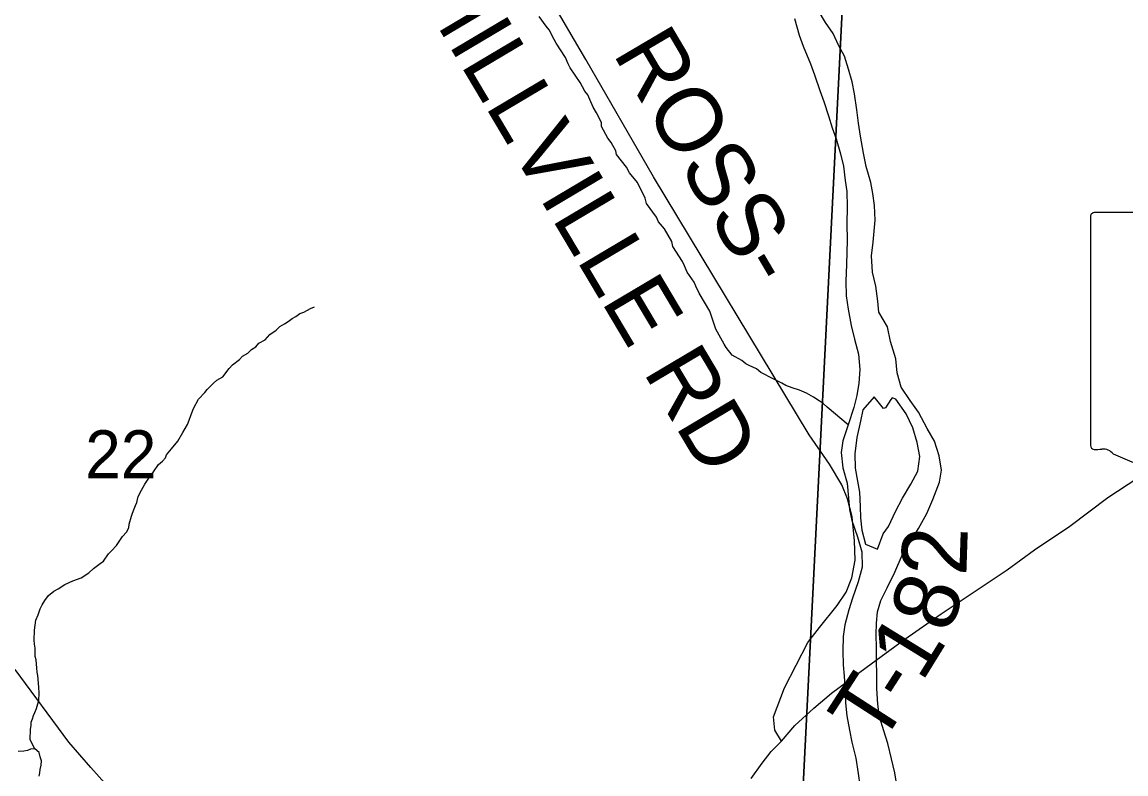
# Model space of a CAD drawing. Extents: x 0 to 34, y -2.3 to 22.
# Drawn here: x 5.851 to 6.815, y 16.564 to 17.221 of the extents above; entities that cross this region are included whole.
import ezdxf

# ---------------------------------------------------------------- set-up
doc = ezdxf.new("R2010")
doc.units = 0
for name, color, linetype in [('GM_X_Major_River', 7, 'Continuous'), ('GM_X_Minor_River', 7, 'Continuous'), ('GM_X_Section', 7, 'Continuous'), ('GM_X_Section_Text', 7, 'Continuous'), ('GM_X_State_Route', 7, 'Continuous'), ('GM_X_State_Shield', 7, 'Continuous'), ('GM_X_Township_Road', 7, 'Continuous'), ('GM_X_Township_Road_Text', 7, 'Continuous')]:
    doc.layers.add(name, color=color, linetype=linetype)

msp = doc.modelspace()

# ---------------------------------------------------------------- linework, layer by layer
at = {"layer": 'GM_X_Major_River'}
for p, q in [((6.55311, 17.22065), (6.54658, 17.23149)), ((6.52585, 17.22411), (6.52997, 17.20954)), ((6.55966, 17.21095), (6.55311, 17.22065)), ((6.52997, 17.20954), (6.53349, 17.19993)), ((6.5643, 17.20093), (6.55966, 17.21095)), ((6.53349, 17.19993), (6.53988, 17.18453)), ((6.56972, 17.19126), (6.5643, 17.20093)), ((6.53988, 17.18453), (6.5434, 17.17492)), ((6.57318, 17.17975), (6.56972, 17.19126)), ((6.5434, 17.17492), (6.54793, 17.1611)), ((6.57627, 17.16864), (6.57318, 17.17975)), ((6.57825, 17.15831), (6.57627, 17.16864)), ((6.54793, 17.1611), (6.55145, 17.15149)), ((6.58049, 17.14417), (6.57825, 17.15831)), ((6.55145, 17.15149), (6.55564, 17.1392)), ((6.55564, 17.1392), (6.55875, 17.12846)), ((6.58167, 17.13273), (6.58049, 17.14417)), ((6.55875, 17.12846), (6.56226, 17.11885)), ((6.58361, 17.12127), (6.58167, 17.13273)), ((6.56226, 17.11885), (6.56606, 17.10581)), ((6.58621, 17.10636), (6.58361, 17.12127)), ((6.58854, 17.09489), (6.58621, 17.10636)), ((6.56606, 17.10581), (6.56878, 17.09509)), ((6.56878, 17.09509), (6.57031, 17.08249)), ((6.59268, 17.0807), (6.58854, 17.09489)), ((6.57031, 17.08249), (6.57155, 17.07295)), ((6.5943, 17.07114), (6.59268, 17.0807)), ((6.57155, 17.07295), (6.57192, 17.05963)), ((6.59589, 17.06083), (6.5943, 17.07114)), ((6.57192, 17.05963), (6.57148, 17.04481)), ((6.59627, 17.04789), (6.59589, 17.06083)), ((6.57148, 17.04481), (6.57182, 17.03035)), ((6.59456, 17.02854), (6.59561, 17.0384)), ((6.59561, 17.0384), (6.59627, 17.04789)), ((6.57182, 17.03035), (6.57119, 17.00908)), ((6.59307, 17.0168), (6.59456, 17.02854)), ((6.59417, 17.00232), (6.59307, 17.0168)), ((6.57119, 17.00908), (6.57076, 16.99464)), ((6.59685, 16.99007), (6.59417, 17.00232)), ((6.57076, 16.99464), (6.57114, 16.9817)), ((6.57114, 16.9817), (6.5727, 16.97025)), ((6.59875, 16.97709), (6.59685, 16.99007)), ((6.5996, 16.96756), (6.59875, 16.97709)), ((6.5727, 16.97025), (6.57532, 16.95572)), ((6.60721, 16.95478), (6.5996, 16.96756)), ((6.57532, 16.95572), (6.57839, 16.94384)), ((6.60986, 16.94178), (6.60721, 16.95478)), ((6.57839, 16.94384), (6.5818, 16.93081)), ((6.61436, 16.92681), (6.60986, 16.94178)), ((6.5818, 16.93081), (6.58293, 16.91747)), ((6.61553, 16.91461), (6.61436, 16.92681)), ((6.58293, 16.91747), (6.58219, 16.90532)), ((6.61895, 16.90196), (6.61553, 16.91461)), ((6.58219, 16.90532), (6.58036, 16.89473)), ((6.58036, 16.89473), (6.57777, 16.88416)), ((6.62697, 16.89032), (6.61895, 16.90196)), ((6.57777, 16.88416), (6.57276, 16.86909)), ((6.59552, 16.89352), (6.58568, 16.88202)), ((6.60358, 16.8834), (6.59552, 16.89352)), ((6.61013, 16.89105), (6.60551, 16.88375)), ((6.61135, 16.89251), (6.61013, 16.89105)), ((6.61446, 16.89145), (6.61135, 16.89251)), ((6.62358, 16.87863), (6.61446, 16.89145)), ((6.63427, 16.88022), (6.62697, 16.89032)), ((6.58568, 16.88202), (6.5835, 16.8722)), ((6.60551, 16.88375), (6.60358, 16.8834)), ((6.6293, 16.86629), (6.62358, 16.87863)), ((6.64183, 16.86593), (6.63427, 16.88022)), ((6.57276, 16.86909), (6.56817, 16.85516)), ((6.5835, 16.8722), (6.58041, 16.85784)), ((6.63311, 16.85363), (6.6293, 16.86629)), ((6.64834, 16.85471), (6.64183, 16.86593)), ((6.56817, 16.85516), (6.56673, 16.84493)), ((6.58041, 16.85784), (6.57848, 16.84383)), ((6.63541, 16.8414), (6.63311, 16.85363)), ((6.65215, 16.84205), (6.64834, 16.85471)), ((6.56673, 16.84493), (6.56824, 16.83158)), ((6.57848, 16.84383), (6.57887, 16.83127)), ((6.63351, 16.82853), (6.63541, 16.8414)), ((6.65443, 16.82943), (6.65215, 16.84205)), ((6.56824, 16.83158), (6.57202, 16.81816)), ((6.57887, 16.83127), (6.58081, 16.8198)), ((6.62748, 16.81729), (6.63351, 16.82853)), ((6.6526, 16.81884), (6.65443, 16.82943)), ((6.57202, 16.81816), (6.57315, 16.80482)), ((6.58081, 16.8198), (6.58281, 16.81024)), ((6.62027, 16.80496), (6.62748, 16.81729)), ((6.64684, 16.8038), (6.6526, 16.81884)), ((6.58281, 16.81024), (6.5832, 16.79768)), ((6.57315, 16.80482), (6.574, 16.79491)), ((6.5832, 16.79768), (6.58367, 16.78778)), ((6.61423, 16.79335), (6.62027, 16.80496)), ((6.64153, 16.7914), (6.64684, 16.8038)), ((6.574, 16.79491), (6.576, 16.78534)), ((6.58367, 16.78778), (6.58487, 16.77709)), ((6.60814, 16.78021), (6.61423, 16.79335)), ((6.63431, 16.77831), (6.64153, 16.7914)), ((6.576, 16.78534), (6.5809, 16.77113)), ((6.6034, 16.77389), (6.60814, 16.78021)), ((6.62593, 16.76486), (6.63431, 16.77831)), ((6.5809, 16.77113), (6.58469, 16.75809)), ((6.58487, 16.77709), (6.58793, 16.76484)), ((6.59844, 16.76035), (6.6034, 16.77389)), ((6.58793, 16.76484), (6.59844, 16.76035)), ((6.61995, 16.75515), (6.62593, 16.76486)), ((6.58469, 16.75809), (6.58506, 16.74477)), ((6.61343, 16.74013), (6.61995, 16.75515)), ((6.58506, 16.74477), (6.58164, 16.73194)), ((6.60695, 16.72663), (6.61343, 16.74013)), ((6.58164, 16.73194), (6.57666, 16.71763)), ((6.60129, 16.71539), (6.60695, 16.72663)), ((6.57666, 16.71763), (6.57332, 16.70746)), ((6.59835, 16.70559), (6.60129, 16.71539)), ((6.57332, 16.70746), (6.56989, 16.69426)), ((6.59768, 16.69572), (6.59835, 16.70559)), ((6.56989, 16.69426), (6.56845, 16.68403)), ((6.59739, 16.68585), (6.59768, 16.69572)), ((6.56845, 16.68403), (6.56808, 16.67149)), ((6.59742, 16.67406), (6.59739, 16.68585)), ((6.59749, 16.66378), (6.59742, 16.67406)), ((6.56808, 16.67149), (6.56848, 16.65931)), ((6.59785, 16.65009), (6.59749, 16.66378)), ((6.56848, 16.65931), (6.56933, 16.6494)), ((6.56933, 16.6494), (6.57007, 16.63569)), ((6.5979, 16.63868), (6.59785, 16.65009)), ((6.57007, 16.63569), (6.57055, 16.62617)), ((6.59863, 16.62496), (6.5979, 16.63868)), ((6.57055, 16.62617), (6.57173, 16.61473)), ((6.60021, 16.61389), (6.59863, 16.62496)), ((6.57173, 16.61473), (6.57402, 16.60211)), ((6.60402, 16.60161), (6.60021, 16.61389)), ((6.57402, 16.60211), (6.576, 16.59179)), ((6.6075, 16.59048), (6.60402, 16.60161)), ((6.576, 16.59179), (6.57938, 16.57762)), ((6.61052, 16.57708), (6.6075, 16.59048)), ((6.57938, 16.57762), (6.58164, 16.56424)), ((6.61358, 16.56483), (6.61052, 16.57708)), ((6.58164, 16.56424), (6.58286, 16.55394)), ((6.61517, 16.55413), (6.61358, 16.56483))]:
    msp.add_line(p, q, dxfattribs=at)
at = {"layer": 'GM_X_Minor_River'}
for p, q in [((6.30907, 17.2174), (6.30286, 17.22595)), ((6.31164, 17.21429), (6.30907, 17.2174)), ((6.31595, 17.2058), (6.31164, 17.21429)), ((6.31776, 17.20271), (6.31595, 17.2058)), ((6.32575, 17.18994), (6.31776, 17.20271)), ((6.32826, 17.18454), (6.32575, 17.18994)), ((6.33006, 17.18107), (6.32826, 17.18454)), ((6.33881, 17.16827), (6.33006, 17.18107)), ((6.34276, 17.16056), (6.33881, 17.16827)), ((6.34533, 17.15744), (6.34276, 17.16056)), ((6.34711, 17.15321), (6.34533, 17.15744)), ((6.34996, 17.14667), (6.34711, 17.15321)), ((6.35285, 17.14164), (6.34996, 17.14667)), ((6.35717, 17.13316), (6.35285, 17.14164)), ((6.35745, 17.12973), (6.35717, 17.13316)), ((6.36286, 17.11969), (6.35745, 17.12973)), ((6.36578, 17.1158), (6.36286, 17.11969)), ((6.36975, 17.10847), (6.36578, 17.1158)), ((6.37042, 17.10541), (6.36975, 17.10847)), ((6.37921, 17.09413), (6.37042, 17.10541)), ((6.38173, 17.08912), (6.37921, 17.09413)), ((6.38871, 17.08093), (6.38173, 17.08912)), ((6.39553, 17.06705), (6.38871, 17.08093)), ((6.39654, 17.06247), (6.39553, 17.06705)), ((6.40531, 17.05043), (6.39654, 17.06247)), ((6.4071, 17.04657), (6.40531, 17.05043)), ((6.41224, 17.04034), (6.4071, 17.04657)), ((6.41875, 17.02913), (6.41224, 17.04034)), ((6.41977, 17.02492), (6.41875, 17.02913)), ((6.42813, 17.01176), (6.41977, 17.02492)), ((6.42992, 17.00791), (6.42813, 17.01176)), ((6.43204, 17.00253), (6.42992, 17.00791)), ((6.43824, 16.9936), (6.43204, 17.00253)), ((6.43966, 16.99014), (6.43824, 16.9936)), ((6.44252, 16.98398), (6.43966, 16.99014)), ((6.45195, 16.9685), (6.44252, 16.98398)), ((6.10308, 16.97059), (6.10654, 16.97201)), ((6.08375, 16.95939), (6.08724, 16.96195)), ((6.08724, 16.96195), (6.09033, 16.96375)), ((6.09033, 16.96375), (6.09383, 16.96631)), ((6.09383, 16.96631), (6.09728, 16.96735)), ((6.09728, 16.96735), (6.10037, 16.96915)), ((6.10037, 16.96915), (6.10308, 16.97059)), ((6.45405, 16.96236), (6.45195, 16.9685)), ((6.4572, 16.95277), (6.45405, 16.96236)), ((6.06745, 16.9481), (6.07326, 16.95173)), ((6.07326, 16.95173), (6.0764, 16.95506)), ((6.0764, 16.95506), (6.08026, 16.95722)), ((6.08026, 16.95722), (6.08375, 16.95939)), ((6.46442, 16.93964), (6.4572, 16.95277)), ((6.05811, 16.94041), (6.06351, 16.94329)), ((6.06351, 16.94329), (6.06745, 16.9481)), ((6.04835, 16.93158), (6.05148, 16.93491)), ((6.05148, 16.93491), (6.05535, 16.93707)), ((6.05535, 16.93707), (6.05811, 16.94041)), ((6.46623, 16.93655), (6.46442, 16.93964)), ((6.47136, 16.92993), (6.46623, 16.93655)), ((6.03512, 16.92135), (6.04096, 16.92611)), ((6.04096, 16.92611), (6.04371, 16.92907)), ((6.04371, 16.92907), (6.04835, 16.93158)), ((6.47996, 16.92512), (6.47136, 16.92993)), ((6.4833, 16.92236), (6.47996, 16.92512)), ((6.02646, 16.91097), (6.032, 16.9184)), ((6.032, 16.9184), (6.03512, 16.92135)), ((6.48629, 16.92075), (6.4833, 16.92236)), ((6.49267, 16.9179), (6.48629, 16.92075)), ((6.49638, 16.91475), (6.49267, 16.9179)), ((6.50013, 16.91312), (6.49638, 16.91475)), ((6.50424, 16.91072), (6.50013, 16.91312)), ((6.01283, 16.89998), (6.01832, 16.90551)), ((6.01832, 16.90551), (6.02143, 16.90808)), ((6.02143, 16.90808), (6.02646, 16.91097)), ((6.51473, 16.90546), (6.50424, 16.91072)), ((6.51848, 16.90345), (6.51473, 16.90546)), ((6.52374, 16.9014), (6.51848, 16.90345)), ((6.00536, 16.89147), (6.01086, 16.89738)), ((6.01086, 16.89738), (6.01283, 16.89998)), ((6.53014, 16.89931), (6.52374, 16.9014)), ((6.53653, 16.89684), (6.53014, 16.89931)), ((6.5425, 16.89324), (6.53653, 16.89684)), ((6.00094, 16.88324), (6.00536, 16.89147)), ((6.54735, 16.89006), (6.5425, 16.89324)), ((6.55108, 16.88766), (6.54735, 16.89006)), ((6.55441, 16.88453), (6.55108, 16.88766)), ((6.57276, 16.86909), (6.55441, 16.88453)), ((5.99723, 16.8731), (5.99849, 16.87724)), ((5.99849, 16.87724), (6.00094, 16.88324)), ((5.99159, 16.86225), (5.9956, 16.86935)), ((5.9956, 16.86935), (5.99723, 16.8731)), ((5.98719, 16.85479), (5.99159, 16.86225)), ((5.97734, 16.84293), (5.98167, 16.84811)), ((5.98167, 16.84811), (5.98719, 16.85479)), ((5.97025, 16.8344), (5.97376, 16.83734)), ((5.97376, 16.83734), (5.9765, 16.84029)), ((5.9765, 16.84029), (5.97734, 16.84293)), ((5.96192, 16.8225), (5.96589, 16.82807)), ((5.96589, 16.82807), (5.97025, 16.8344)), ((5.95553, 16.81205), (5.95835, 16.81728)), ((5.95835, 16.81728), (5.96192, 16.8225)), ((5.95271, 16.80644), (5.95553, 16.81205)), ((5.94897, 16.79553), (5.9502, 16.79854)), ((5.9502, 16.79854), (5.95142, 16.80116)), ((5.95142, 16.80116), (5.95271, 16.80644)), ((5.94479, 16.78236), (5.94689, 16.78914)), ((5.94689, 16.78914), (5.94772, 16.79177)), ((5.94772, 16.79177), (5.94897, 16.79553)), ((5.9423, 16.77522), (5.94431, 16.77896)), ((5.94431, 16.77896), (5.94479, 16.78236)), ((5.9336, 16.76371), (5.93877, 16.77153)), ((5.93877, 16.77153), (5.9423, 16.77522)), ((5.92654, 16.75632), (5.92928, 16.7589)), ((5.92928, 16.7589), (5.9336, 16.76371)), ((5.91946, 16.7478), (5.92218, 16.74999)), ((5.92218, 16.74999), (5.92654, 16.75632)), ((5.90275, 16.73538), (5.90934, 16.73974)), ((5.90934, 16.73974), (5.91363, 16.74341)), ((5.91363, 16.74341), (5.91946, 16.7478)), ((5.88851, 16.72935), (5.89544, 16.73256)), ((5.89544, 16.73256), (5.90275, 16.73538)), ((5.87417, 16.7199), (5.87884, 16.72356)), ((5.87884, 16.72356), (5.8827, 16.72572)), ((5.8827, 16.72572), (5.88851, 16.72935)), ((5.86699, 16.70834), (5.86861, 16.71171)), ((5.86861, 16.71171), (5.871, 16.71544)), ((5.871, 16.71544), (5.87417, 16.7199)), ((5.86327, 16.6982), (5.86532, 16.70307)), ((5.86532, 16.70307), (5.86699, 16.70834)), ((5.86188, 16.6895), (5.86327, 16.6982)), ((5.86163, 16.68077), (5.86188, 16.6895)), ((5.86191, 16.67735), (5.86163, 16.68077)), ((5.86257, 16.67391), (5.86191, 16.67735)), ((5.86274, 16.66668), (5.86257, 16.67391)), ((5.86341, 16.66363), (5.86274, 16.66668)), ((5.86396, 16.65639), (5.86341, 16.66363)), ((5.86424, 16.65296), (5.86396, 16.65639)), ((5.86491, 16.64991), (5.86424, 16.65296)), ((5.8652, 16.64686), (5.86491, 16.64991)), ((5.86575, 16.63962), (5.8652, 16.64686)), ((5.86598, 16.63468), (5.86575, 16.63962)), ((5.86578, 16.62785), (5.86598, 16.63468)), ((5.86369, 16.62107), (5.86495, 16.62521)), ((5.86495, 16.62521), (5.86578, 16.62785)), ((5.86039, 16.61206), (5.86123, 16.61507)), ((5.86123, 16.61507), (5.86245, 16.61769)), ((5.86245, 16.61769), (5.86369, 16.62107)), ((5.8586, 16.60299), (5.85908, 16.6064)), ((5.85908, 16.6064), (5.85916, 16.60905)), ((5.85916, 16.60905), (5.86039, 16.61206)), ((5.85833, 16.59388), (5.8586, 16.60299)), ((5.85847, 16.58552), (5.85578, 16.58446)), ((5.86228, 16.58579), (5.85833, 16.59388)), ((5.86228, 16.58579), (5.85847, 16.58552)), ((5.86599, 16.58264), (5.86228, 16.58579)), ((5.85272, 16.5838), (5.84777, 16.58356)), ((5.85578, 16.58446), (5.85272, 16.5838)), ((5.86702, 16.57881), (5.86599, 16.58264)), ((5.86806, 16.57536), (5.86702, 16.57881)), ((5.86661, 16.56477), (5.86708, 16.56779)), ((5.86708, 16.56779), (5.86795, 16.57156)), ((5.86795, 16.57156), (5.86806, 16.57536)), ((5.86615, 16.56212), (5.86661, 16.56477))]:
    msp.add_line(p, q, dxfattribs=at)
at = {"layer": 'GM_X_Section'}
for p, q in [((6.57262, 17.33501), (6.52343, 16.35426)), ((6.52343, 16.35426), (6.57262, 17.33501))]:
    msp.add_line(p, q, dxfattribs=at)
at = {"layer": 'GM_X_State_Route'}
for p, q in [((6.79954, 16.80563), (6.82568, 16.82284)), ((6.76648, 16.78061), (6.79954, 16.80563)), ((6.73543, 16.75984), (6.76648, 16.78061)), ((6.71158, 16.7424), (6.73543, 16.75984)), ((6.68628, 16.72544), (6.71158, 16.7424)), ((6.6539, 16.704), (6.68628, 16.72544)), ((6.62224, 16.68162), (6.6539, 16.704)), ((6.58862, 16.65702), (6.62224, 16.68162)), ((6.5581, 16.63461), (6.58862, 16.65702)), ((6.54287, 16.62156), (6.5581, 16.63461)), ((6.52611, 16.60637), (6.54287, 16.62156)), ((6.51464, 16.59264), (6.52611, 16.60637)), ((6.50551, 16.58369), (6.50758, 16.58572)), ((6.50758, 16.58572), (6.51464, 16.59264)), ((6.49754, 16.57343), (6.50551, 16.58369)), ((6.4881, 16.55992), (6.49754, 16.57343))]:
    msp.add_line(p, q, dxfattribs=at)
at = {"layer": 'GM_X_State_Shield'}
for p, q in [((6.78457, 17.0511), (6.78457, 16.85098)), ((6.88434, 17.05454), (6.78782, 17.05454))]:
    msp.add_line(p, q, dxfattribs=at)
for centre, major_axis, start_param, end_param in [((6.78835, 17.05153), (0.00382, 0), 1.712693, 3.28349), ((6.78838, 16.85054), (0.00385, 0), 3.00124, 4.508301), ((6.78897, 16.87101), (0.0294, 0), 4.665946, 4.897461), ((6.79498, 16.83943), (0.0106, 0), 0.519207, 1.627899), ((6.92881, 17.01923), (0.2524, 0), 4.195997, 4.488961)]:
    msp.add_ellipse(centre, major_axis=major_axis, ratio=0.8, start_param=start_param, end_param=end_param, dxfattribs=at)
at = {"layer": 'GM_X_Township_Road'}
for p, q in [((6.34367, 17.18816), (6.30704, 17.25101)), ((6.40278, 17.08583), (6.34367, 17.18816)), ((6.53873, 16.86032), (6.40278, 17.08583)), ((6.55648, 16.8346), (6.53873, 16.86032)), ((6.56723, 16.81668), (6.55648, 16.8346)), ((6.57211, 16.80431), (6.56723, 16.81668)), ((6.57618, 16.78852), (6.57211, 16.80431)), ((6.57846, 16.76768), (6.57618, 16.78852)), ((6.57895, 16.75074), (6.57846, 16.76768)), ((6.57585, 16.73544), (6.57895, 16.75074)), ((6.57113, 16.7229), (6.57585, 16.73544)), ((6.56315, 16.71118), (6.57113, 16.7229)), ((6.54769, 16.6918), (6.56315, 16.71118)), ((6.53759, 16.67878), (6.54769, 16.6918)), ((6.51724, 16.63921), (6.53759, 16.67878)), ((5.89191, 16.59166), (5.84519, 16.65529)), ((6.50763, 16.61381), (6.51724, 16.63921)), ((6.50877, 16.60225), (6.50763, 16.61381)), ((6.51464, 16.59264), (6.50877, 16.60225)), ((5.91112, 16.56944), (5.89191, 16.59166)), ((5.92576, 16.55322), (5.91112, 16.56944))]:
    msp.add_line(p, q, dxfattribs=at)

# ---------------------------------------------------------------- texts
at = {"layer": 'GM_X_Section_Text'}
msp.add_text('22', height=0.041856, rotation=0.00001, dxfattribs=at).set_placement((5.9063, 16.82238))
at = {"layer": 'GM_X_Township_Road_Text'}
for s, height, rotation, p in [('MILLVILLE RD', 0.0568182, 300.71037, (6.19033, 17.25686)), ('ROSS-', 0.056818, 300.55082, (6.36657, 17.1939)), ('2', 0.05682, 88.11117, (6.67597, 16.73664)), ('8', 0.05682, 71.20924, (6.66143, 16.6856)), ('1', 0.05682, 58.31988, (6.63712, 16.64323)), ('T', 0.05682, 57.13782, (6.60079, 16.5868)), ('-', 0.05682, 57.35468, (6.62398, 16.6227))]:
    msp.add_text(s, height=height, rotation=rotation, dxfattribs=at).set_placement(p)

doc.saveas('drawing.dxf')
